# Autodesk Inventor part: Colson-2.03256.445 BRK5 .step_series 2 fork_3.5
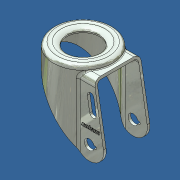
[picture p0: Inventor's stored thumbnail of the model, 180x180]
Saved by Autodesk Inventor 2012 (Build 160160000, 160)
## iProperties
Created: 2010-10
Part Number: Colson-2.03256.445 BRK5 .step_series 2 fork_3.5
Document SubType Name: Modeling
Designer: Administrator
Density: 7.85 g/cm^3
Material: Steel
Mass: 181.925 g
Surface Area: 201.14 cm^2
Volume: 23.1752 cm^3
Author: Administrator
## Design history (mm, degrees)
feature "Base1"
body "Solid1"
